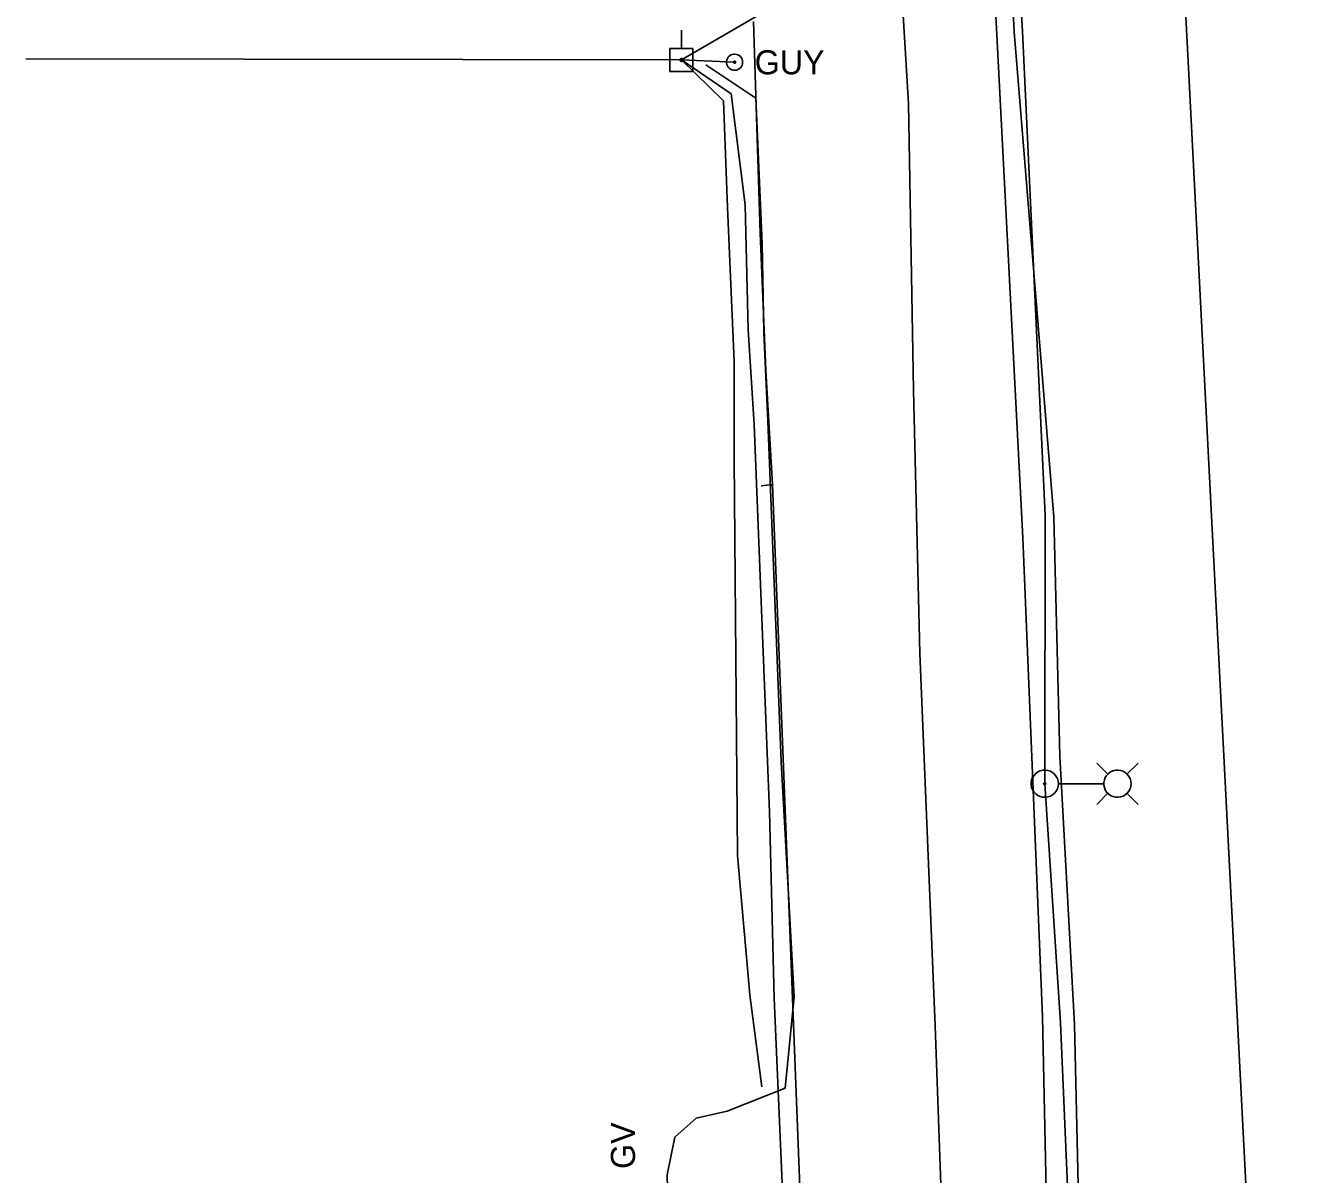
# Model space of a CAD drawing. Extents: x 600849 to 606371, y 330010 to 403088.
# Drawn here: x 604678.1 to 604884.2, y 334987.6 to 335171 of the extents above; entities that cross this region are included whole.
import ezdxf

# ---------------------------------------------------------------- set-up
doc = ezdxf.new("R2010")
doc.units = 0
for name, color, linetype in [('E_FTMS_Conduit', 7, 'Continuous'), ('E_LTG', 7, 'Continuous'), ('E_LTG_CID', 7, 'Continuous'), ('E_UTL_E_UG', 7, 'Continuous'), ('E_UTL_EGuyWire', 7, 'Continuous'), ('E_UTL_EPowerPole', 7, 'Continuous'), ('E_UTL_FO_UG', 7, 'Continuous'), ('E_UTL_FO_UG_QWEST', 7, 'Continuous'), ('E_UTL_G', 7, 'Continuous'), ('E_UTL_Overhead', 7, 'Continuous'), ('E_UTL_SAN_UG_MMSD', 7, 'Continuous'), ('E_UTL_T_UG', 7, 'Continuous'), ('E_UTL_TV_UG', 7, 'Continuous'), ('E_UTL_W_UG', 7, 'Continuous')]:
    doc.layers.add(name, color=color, linetype=linetype)

msp = doc.modelspace()

# ---------------------------------------------------------------- linework, layer by layer
at = {"layer": 'E_FTMS_Conduit'}
msp.add_lwpolyline([(604865.66, 334623.82), (604860.3, 334662.92), (604859.68, 334742.73), (604857.4, 334780.45), (604853.68, 334856.29), (604850.24, 334895.79), (604847.27, 334936.94), (604845.54, 335011.51), (604843.22, 335054.36), (604842.26, 335092.55), (604835.93, 335170.05), (604833.24, 335224.35), (604834.53, 335254.76), (604831.45, 335295.34), (604820.14, 335431.05), (604817.01, 335471.26), (604813.1, 335515.04), (604806.53, 335560.93), (604800.96, 335611.56)], dxfattribs=at)
at = {"layer": 'E_LTG'}
for points in [[(604842.99, 335049.96), (604842.95, 335050.37), (604842.83, 335050.77), (604842.64, 335051.14), (604842.38, 335051.46), (604842.07, 335051.73), (604841.71, 335051.94), (604841.32, 335052.07), (604840.91, 335052.13), (604840.5, 335052.11), (604840.1, 335052.02), (604839.72, 335051.84), (604839.39, 335051.6), (604839.1, 335051.3), (604838.88, 335050.96), (604838.72, 335050.57), (604838.64, 335050.17), (604838.64, 335049.75), (604838.72, 335049.35), (604838.88, 335048.96), (604839.1, 335048.61), (604839.39, 335048.32), (604839.72, 335048.08), (604840.1, 335047.9), (604840.5, 335047.81), (604840.91, 335047.79), (604841.32, 335047.85), (604841.71, 335047.98), (604842.07, 335048.19), (604842.38, 335048.46), (604842.64, 335048.78), (604842.83, 335049.15), (604842.95, 335049.55), (604842.99, 335049.96)], [(604850.89, 335051.49), (604849.11, 335053.26)], [(604854.59, 335049.96), (604854.55, 335050.37), (604854.43, 335050.77), (604854.24, 335051.14), (604853.99, 335051.46), (604853.68, 335051.73), (604853.32, 335051.94), (604852.93, 335052.07), (604852.52, 335052.13), (604852.1, 335052.11), (604851.7, 335052.02), (604851.33, 335051.84), (604850.99, 335051.6), (604850.7, 335051.3), (604850.48, 335050.96), (604850.33, 335050.57), (604850.25, 335050.17), (604850.25, 335049.75), (604850.33, 335049.35), (604850.48, 335048.96), (604850.7, 335048.61), (604850.99, 335048.32), (604851.33, 335048.08), (604851.7, 335047.9), (604852.1, 335047.81), (604852.52, 335047.79), (604852.93, 335047.85), (604853.32, 335047.98), (604853.68, 335048.19), (604853.99, 335048.46), (604854.24, 335048.78), (604854.43, 335049.15), (604854.55, 335049.55), (604854.59, 335049.96)], [(604853.94, 335051.49), (604855.72, 335053.26)], [(604840.98, 335049.96), (604840.97, 335049.99), (604840.96, 335050.02), (604840.95, 335050.05), (604840.93, 335050.07), (604840.91, 335050.1), (604840.88, 335050.11), (604840.85, 335050.12), (604840.82, 335050.13), (604840.79, 335050.12), (604840.76, 335050.12), (604840.73, 335050.1), (604840.7, 335050.09), (604840.68, 335050.06), (604840.66, 335050.04), (604840.65, 335050.01), (604840.64, 335049.98), (604840.64, 335049.94), (604840.65, 335049.91), (604840.66, 335049.88), (604840.68, 335049.86), (604840.7, 335049.83), (604840.73, 335049.82), (604840.76, 335049.8), (604840.79, 335049.8), (604840.82, 335049.79), (604840.85, 335049.8), (604840.88, 335049.81), (604840.91, 335049.82), (604840.93, 335049.85), (604840.95, 335049.87), (604840.96, 335049.9), (604840.97, 335049.93), (604840.98, 335049.96)], [(604850.2, 335049.96), (604843.02, 335049.96)], [(604850.89, 335048.44), (604849.11, 335046.66)], [(604853.94, 335048.44), (604855.72, 335046.66)]]:
    msp.add_lwpolyline(points, dxfattribs=at)
at = {"layer": 'E_LTG_CID'}
msp.add_lwpolyline([(604862.3, 334623.54), (604859.11, 334663.85), (604858.92, 334663.88), (604858.21, 334688.84), (604855.44, 334742.39), (604854.47, 334780.17), (604850.82, 334856.89), (604849.46, 334868.66), (604849.2, 334895.58), (604846.51, 334937.17), (604843.31, 335011.75), (604840.81, 335049.96), (604840.88, 335092.82), (604837.28, 335170.14), (604834.71, 335212.97)], dxfattribs=at)
at = {"layer": 'E_UTL_E_UG'}
msp.add_lwpolyline([(604841.27, 334614.96), (604838.91, 334672.58), (604835.72, 334731.86), (604833.33, 334793.2), (604830.28, 334854.41), (604827.22, 334896.47), (604825.25, 334968.56), (604825.04, 334973.69), (604824.51, 334978.47), (604823.31, 335011.26), (604820.86, 335070.81), (604819.86, 335112.84), (604819.04, 335158.63), (604817.07, 335191.32), (604814.49, 335235.91), (604811.85, 335279.29), (604809.46, 335325.61), (604807.12, 335373), (604804.05, 335421.46), (604799.37, 335470.45), (604793.24, 335522.54), (604789.06, 335554.45), (604783.73, 335590.4)], dxfattribs=at)
at = {"layer": 'E_UTL_EGuyWire'}
msp.add_line((604791.28, 335165.21), (604782.82, 335165.57), dxfattribs=at)
for points in [[(604792.56, 335165.21), (604792.54, 335165.45), (604792.47, 335165.69), (604792.36, 335165.9), (604792.21, 335166.1), (604792.02, 335166.26), (604791.81, 335166.38), (604791.58, 335166.46), (604791.34, 335166.49), (604791.1, 335166.48), (604790.86, 335166.42), (604790.64, 335166.32), (604790.44, 335166.18), (604790.27, 335166), (604790.14, 335165.8), (604790.05, 335165.57), (604790, 335165.33), (604790, 335165.09), (604790.05, 335164.85), (604790.14, 335164.62), (604790.27, 335164.42), (604790.44, 335164.24), (604790.64, 335164.1), (604790.86, 335164), (604791.1, 335163.94), (604791.34, 335163.93), (604791.58, 335163.96), (604791.81, 335164.04), (604792.02, 335164.16), (604792.21, 335164.32), (604792.36, 335164.52), (604792.47, 335164.73), (604792.54, 335164.97), (604792.56, 335165.21)], [(604791.44, 335165.21), (604791.44, 335165.24), (604791.43, 335165.27), (604791.42, 335165.3), (604791.4, 335165.32), (604791.37, 335165.34), (604791.35, 335165.36), (604791.32, 335165.37), (604791.29, 335165.37), (604791.26, 335165.37), (604791.23, 335165.36), (604791.2, 335165.35), (604791.18, 335165.33), (604791.15, 335165.31), (604791.14, 335165.28), (604791.13, 335165.25), (604791.12, 335165.22), (604791.12, 335165.19), (604791.13, 335165.16), (604791.14, 335165.14), (604791.15, 335165.11), (604791.18, 335165.09), (604791.2, 335165.07), (604791.23, 335165.06), (604791.26, 335165.05), (604791.29, 335165.05), (604791.32, 335165.05), (604791.35, 335165.06), (604791.37, 335165.08), (604791.4, 335165.1), (604791.42, 335165.12), (604791.43, 335165.15), (604791.44, 335165.18), (604791.44, 335165.21)]]:
    msp.add_lwpolyline(points, dxfattribs=at)
at = {"layer": 'E_UTL_EPowerPole'}
for points in [[(604782.78, 335167.41), (604782.78, 335170.32)], [(604784.63, 335167.41), (604780.94, 335167.41)], [(604780.94, 335167.41), (604780.94, 335163.72)], [(604784.63, 335163.72), (604784.63, 335167.41)], [(604783.05, 335165.57), (604783.05, 335165.61), (604783.04, 335165.66), (604783.02, 335165.7), (604782.99, 335165.73), (604782.95, 335165.76), (604782.91, 335165.79), (604782.87, 335165.8), (604782.83, 335165.81), (604782.78, 335165.81), (604782.74, 335165.79), (604782.7, 335165.78), (604782.66, 335165.75), (604782.63, 335165.72), (604782.6, 335165.68), (604782.59, 335165.64), (604782.58, 335165.59), (604782.58, 335165.55), (604782.59, 335165.5), (604782.6, 335165.46), (604782.63, 335165.42), (604782.66, 335165.39), (604782.7, 335165.36), (604782.74, 335165.34), (604782.78, 335165.33), (604782.83, 335165.33), (604782.87, 335165.34), (604782.91, 335165.35), (604782.95, 335165.38), (604782.99, 335165.4), (604783.02, 335165.44), (604783.04, 335165.48), (604783.05, 335165.52), (604783.05, 335165.57)], [(604780.94, 335163.72), (604784.63, 335163.72)]]:
    msp.add_lwpolyline(points, dxfattribs=at)
at = {"layer": 'E_UTL_FO_UG'}
msp.add_lwpolyline([(604795.64, 335001.53), (604793.74, 335016.26), (604791.77, 335038.47), (604791.24, 335101.82), (604791.24, 335117.43), (604790.13, 335142.02), (604789.51, 335159.07), (604782.82, 335165.57)], dxfattribs=at)
at = {"layer": 'E_UTL_FO_UG_QWEST'}
msp.add_lwpolyline([(604880.24, 334183.25), (604876.98, 334256.9), (604873.2, 334330.88), (604873.06, 334361.71), (604869.66, 334408.48), (604865.91, 334483.81), (604863.36, 334557.53), (604860.02, 334633.27), (604855.03, 334705.91), (604850.49, 334782.01), (604846.38, 334856.9), (604842.05, 334937.04), (604840.43, 335012.73), (604837.31, 335089.26), (604832.93, 335173.7), (604830.71, 335249.27), (604828.33, 335311.14), (604825.79, 335353.18), (604822.55, 335385.33), (604819.59, 335404.65), (604816.19, 335465.69), (604807.94, 335539.85), (604801.77, 335593.87)], dxfattribs=at)
at = {"layer": 'E_UTL_Overhead'}
for points in [[(604782.82, 335165.57), (605004.43, 335294.31)], [(604678.09, 335165.76), (604782.82, 335165.57)]]:
    msp.add_lwpolyline(points, dxfattribs=at)
at = {"layer": 'E_UTL_SAN_UG_MMSD'}
msp.add_line((604889.58, 334663.41), (604856.43, 335306.2), dxfattribs=at)
at = {"layer": 'E_UTL_T_UG'}
msp.add_lwpolyline([(604781.19, 334955.24), (604781.26, 334956.9), (604780.52, 334987.51), (604781.76, 334993.48), (604785.16, 334996.51), (604790.1, 334997.63), (604799.35, 335001.31), (604800.8, 335015.92), (604798.74, 335053.44), (604796.57, 335107.86), (604795.96, 335122.04), (604795.68, 335136.2), (604794.7, 335159.47), (604786.68, 335164.8)], dxfattribs=at)
at = {"layer": 'E_UTL_TV_UG'}
msp.add_lwpolyline([(604817.34, 334644.42), (604816.08, 334676.3), (604813.81, 334728.2), (604809.39, 334794.06), (604807.73, 334857.81), (604805.23, 334914.65), (604801.05, 334950.32), (604798.9, 334986.15), (604797.61, 335015.7), (604796.88, 335045.48), (604794.41, 335107.34), (604793.45, 335122.45), (604792.96, 335142.41), (604790.74, 335160.15), (604782.82, 335165.57)], dxfattribs=at)
at = {"layer": 'E_UTL_W_UG'}
for points in [[(604797.31, 335097.75), (604796.29, 335115.98), (604795.35, 335137.98), (604794.29, 335171.74)], [(604797.31, 335097.75), (604795.51, 335097.57)], [(604846.62, 333845.73), (604845.91, 333962.63), (604845.14, 333993.13), (604845.77, 334042.88), (604845.13, 334077.17), (604842.87, 334162.23), (604837.44, 334211.69), (604837.01, 334265.02), (604832.72, 334352.02), (604829.86, 334407.8), (604827.89, 334453.7), (604825.43, 334498.81), (604822.75, 334554.4), (604821.56, 334581.06), (604817.29, 334667.8), (604815.06, 334708.63), (604813.04, 334742.82), (604812.12, 334767.3), (604810.04, 334815.66), (604808.35, 334858.79), (604805.32, 334921.82), (604804.92, 334936.69), (604802.65, 334960.89), (604797.31, 335097.75)]]:
    msp.add_lwpolyline(points, dxfattribs=at)

# ---------------------------------------------------------------- texts
at = {"layer": 'E_UTL_EGuyWire'}
msp.add_text('GUY', height=3.85, dxfattribs=at).set_placement((604794.49, 335163.28))
at = {"layer": 'E_UTL_G'}
msp.add_text('GV', height=3.85, rotation=90, dxfattribs=at).set_placement((604775.38, 334988.42))

doc.saveas('drawing.dxf')
